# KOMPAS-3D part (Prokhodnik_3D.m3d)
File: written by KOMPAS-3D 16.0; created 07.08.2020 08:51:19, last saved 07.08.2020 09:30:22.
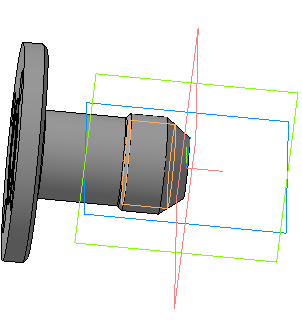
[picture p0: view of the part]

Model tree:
1. Эскиз:1
2. Операция вращения:1
     Угол 1 = 360
3. Эскиз:2
4. Операция выдавливания:1
     Расстояние 1 = 6
5. Эскиз:3
6. Вырезать элемент выдавливания:1
     Расстояние 1 = 55
7. Эскиз:4
8. Вырезать элемент выдавливания:2
     Расстояние 1 = 1.85
9. Скругление:1
     Радиус = 0.4
10. Скругление:2
     Радиус = 0.2
11. Скругление:3
     Радиус = 1
12. Скругление:4
     Радиус = 0.5
13. Фаска:1
     Угол = 45; Длина 1 = 1; Длина 2 = 1
14. Вырезать элемент выдавливания:3
     Расстояние 1 = 550
15. Условное изображение резьбы:1  (labels: ..\..\..\..\..\КОМПАС\Sys\Thread\cil0_8724-2002 coarse.xml; C:\КОМПАС\Sys\Thread\cil0_8724-2002 coarse.xml; M24)
     Длина резьбы = 12.1694; Шаг резьбы = 3; Номинальный диаметр резьбы = 24
16. Подгонка:1

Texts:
  mal0y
